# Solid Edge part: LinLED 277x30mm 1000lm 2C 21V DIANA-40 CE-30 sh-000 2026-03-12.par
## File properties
Author: robert.pupel
Template: iso metric part.par
Last saved by: robert.pupel
Revision: 1
Application: Solid Edge
Gęstość: 0.000 kg/m^3
Dokładność: 0.990
Username: robert.pupel
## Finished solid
Body 1: solid body, 14 faces, 28 edges, 16 vertices.
  Faces by surface: plane 14
  Edges by curve: line 28
Body 2: solid body, 14 faces, 28 edges, 16 vertices.
  Faces by surface: plane 14
  Edges by curve: line 28
Body 3: solid body, 67 faces, 258 edges, 194 vertices.
  Faces by surface: plane 55, cylinder 12
  Edges by curve: line 148, curve on surface 90, circle 12, ellipse 8
Body 4: solid body, 67 faces, 258 edges, 194 vertices.
  Faces by surface: plane 55, cylinder 12
  Edges by curve: line 148, curve on surface 90, circle 12, ellipse 8
Body 5: solid body, 67 faces, 258 edges, 194 vertices.
  Faces by surface: plane 55, cylinder 12
  Edges by curve: line 148, curve on surface 90, circle 12, ellipse 8
Body 6: solid body, 67 faces, 258 edges, 194 vertices.
  Faces by surface: plane 55, cylinder 12
  Edges by curve: line 148, curve on surface 90, circle 12, ellipse 8
Body 7: solid body, 67 faces, 258 edges, 194 vertices.
  Faces by surface: plane 55, cylinder 12
  Edges by curve: line 148, curve on surface 90, circle 12, ellipse 8
Body 8: solid body, 67 faces, 258 edges, 194 vertices.
  Faces by surface: plane 55, cylinder 12
  Edges by curve: line 148, curve on surface 90, circle 12, ellipse 8
Body 9: solid body, 67 faces, 258 edges, 194 vertices.
  Faces by surface: plane 55, cylinder 12
  Edges by curve: line 148, curve on surface 90, circle 12, ellipse 8
Body 10: solid body, 67 faces, 258 edges, 194 vertices.
  Faces by surface: plane 55, cylinder 12
  Edges by curve: line 148, curve on surface 90, circle 12, ellipse 8
Body 11: solid body, 67 faces, 258 edges, 194 vertices.
  Faces by surface: plane 55, cylinder 12
  Edges by curve: line 148, curve on surface 90, circle 12, ellipse 8
Body 12: solid body, 67 faces, 258 edges, 194 vertices.
  Faces by surface: plane 55, cylinder 12
  Edges by curve: line 148, curve on surface 90, circle 12, ellipse 8
Body 13: solid body, 67 faces, 258 edges, 194 vertices.
  Faces by surface: plane 55, cylinder 12
  Edges by curve: line 148, curve on surface 90, circle 12, ellipse 8
Body 14: solid body, 67 faces, 258 edges, 194 vertices.
  Faces by surface: plane 55, cylinder 12
  Edges by curve: line 148, curve on surface 90, circle 12, ellipse 8
Body 15: solid body, 67 faces, 258 edges, 194 vertices.
  Faces by surface: plane 55, cylinder 12
  Edges by curve: line 148, curve on surface 90, circle 12, ellipse 8
Body 16: solid body, 67 faces, 258 edges, 194 vertices.
  Faces by surface: plane 55, cylinder 12
  Edges by curve: line 148, curve on surface 90, circle 12, ellipse 8
Body 17: solid body, 67 faces, 258 edges, 194 vertices.
  Faces by surface: plane 55, cylinder 12
  Edges by curve: line 148, curve on surface 90, circle 12, ellipse 8
Body 18: solid body, 67 faces, 258 edges, 194 vertices.
  Faces by surface: plane 55, cylinder 12
  Edges by curve: line 148, curve on surface 90, circle 12, ellipse 8
Body 19: solid body, 67 faces, 258 edges, 194 vertices.
  Faces by surface: plane 55, cylinder 12
  Edges by curve: line 148, curve on surface 90, circle 12, ellipse 8
Body 20: solid body, 67 faces, 258 edges, 194 vertices.
  Faces by surface: plane 55, cylinder 12
  Edges by curve: line 148, curve on surface 90, circle 12, ellipse 8
Body 21: solid body, 67 faces, 258 edges, 194 vertices.
  Faces by surface: plane 55, cylinder 12
  Edges by curve: line 148, curve on surface 90, circle 12, ellipse 8
Body 22: solid body, 67 faces, 258 edges, 194 vertices.
  Faces by surface: plane 55, cylinder 12
  Edges by curve: line 148, curve on surface 90, circle 12, ellipse 8
Body 23: solid body, 67 faces, 258 edges, 194 vertices.
  Faces by surface: plane 55, cylinder 12
  Edges by curve: line 148, curve on surface 90, circle 12, ellipse 8
Body 24: solid body, 67 faces, 258 edges, 194 vertices.
  Faces by surface: plane 55, cylinder 12
  Edges by curve: line 148, curve on surface 90, circle 12, ellipse 8
Body 25: solid body, 67 faces, 258 edges, 194 vertices.
  Faces by surface: plane 55, cylinder 12
  Edges by curve: line 148, curve on surface 90, circle 12, ellipse 8
Body 26: solid body, 67 faces, 258 edges, 194 vertices.
  Faces by surface: plane 55, cylinder 12
  Edges by curve: line 148, curve on surface 90, circle 12, ellipse 8
Body 27: solid body, 67 faces, 258 edges, 194 vertices.
  Faces by surface: plane 55, cylinder 12
  Edges by curve: line 148, curve on surface 90, circle 12, ellipse 8
Body 28: solid body, 67 faces, 258 edges, 194 vertices.
  Faces by surface: plane 55, cylinder 12
  Edges by curve: line 148, curve on surface 90, circle 12, ellipse 8
Body 29: solid body, 67 faces, 258 edges, 194 vertices.
  Faces by surface: plane 55, cylinder 12
  Edges by curve: line 148, curve on surface 90, circle 12, ellipse 8
Body 30: solid body, 67 faces, 258 edges, 194 vertices.
  Faces by surface: plane 55, cylinder 12
  Edges by curve: line 148, curve on surface 90, circle 12, ellipse 8
Body 31: solid body, 238 faces, 593 edges, 366 vertices.
  Faces by surface: plane 95, cylinder 65, torus 32, cone 25, spline 13, sphere 8
  Edges by curve: line 289, curve on surface 178, circle 75, ellipse 33, spline 18
Body 32: solid body, 238 faces, 593 edges, 366 vertices.
  Faces by surface: plane 95, cylinder 65, torus 32, cone 25, spline 13, sphere 8
  Edges by curve: line 289, curve on surface 178, circle 75, ellipse 33, spline 18
Body 33: solid body, 77 faces, 206 edges, 138 vertices.
  Faces by surface: plane 52, cylinder 25
  Edges by curve: line 92, spline 48, circle 34, curve on surface 32
Bounding box of the edges (mm; curved faces can reach further): 277.000 x 4.450 x 30.000, from (-138.5, -3.45, -15) to (138.5, 1, 15).
Cylindrical faces by radius (mm): R0.2 x270, R0.2169 x6, R0.25 x96, R0.3373 x6, R0.35 x28, R0.4 x8, R0.4006 x2, R0.4008 x2, R0.525 x2, R0.6 x20, R1 x8, R1.025 x8, R1.05 x1, R1.1 x4, R1.1989 x2, R1.199 x2, R1.2 x10, R1.5309 x2, R1.5312 x2, R1.65 x8, R1.7414 x2, R1.7423 x2
Conical faces (half-angle, radius in mm at the cone's reference point): 0.398 deg R1.1964 x2, 0.4493 deg R1.1964 x2, 0.4746 deg R1.1948 x2, 0.4758 deg R1.1948 x2, 0.5 deg R0.5056 x4, 0.5 deg R1.0082 x4, 1 deg R0.5511 x2, 10 deg R0.2132 x4, 10 deg R0.4132 x4, 16.0099 deg R1.1053 x2, 16.1249 deg R1.1279 x2, 18.8604 deg R1.0669 x4, 19.5041 deg R0.5138 x2, 19.8244 deg R0.5099 x2, 27.363 deg R0.6214 x2, 40.6434 deg R0.5161 x2, 43.3309 deg R0.4892 x2, 45 deg R0.575 x2, 45 deg R0.625 x4
Toroidal faces (ring radius, tube radius in mm): R0.0958 r0.3997 x4, R0.1076 r0.4 x2, R0.1101 r0.4001 x2, R0.1217 r0.4 x2, R0.1234 r0.4 x2, R0.1626 r0.228 x2, R0.1634 r0.2287 x2, R0.3287 r0.2001 x2, R0.3684 r0.2151 x2, R0.3703 r0.4 x2, R0.3818 r0.2 x4, R0.4166 r0.3983 x2, R0.5981 r0.197 x2, R0.5982 r0.197 x2, R0.6009 r0.3968 x2, R0.6009 r0.3969 x2, R0.6227 r0.2 x2, R0.6235 r0.2 x2, R0.8 r0.2 x4, R0.8522 r0.3 x2, R0.9002 r0.2 x2, R0.9018 r0.2 x2, R0.9197 r0.223 x2, R0.9365 r0.2 x2, R0.9663 r0.2263 x2, R0.9665 r0.2263 x2, R1.429 r1.2 x2, R1.8741 r0.2175 x2, R1.9007 r0.2 x2
Spherical faces by radius (mm): R0.2 x12, R0.6 x4
Planar faces by outward normal: +x 246, +y 159, +z 319, -x 246, -y 289, -z 319, oblique 232
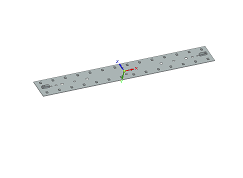
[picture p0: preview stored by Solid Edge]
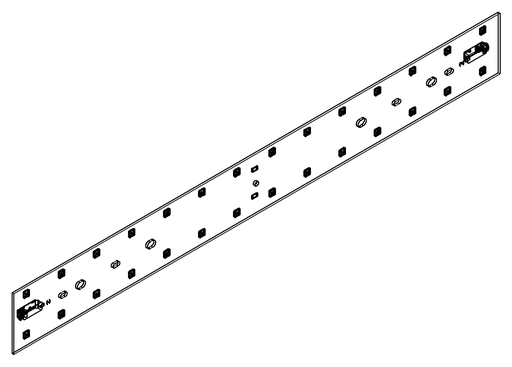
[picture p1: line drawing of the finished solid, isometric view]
